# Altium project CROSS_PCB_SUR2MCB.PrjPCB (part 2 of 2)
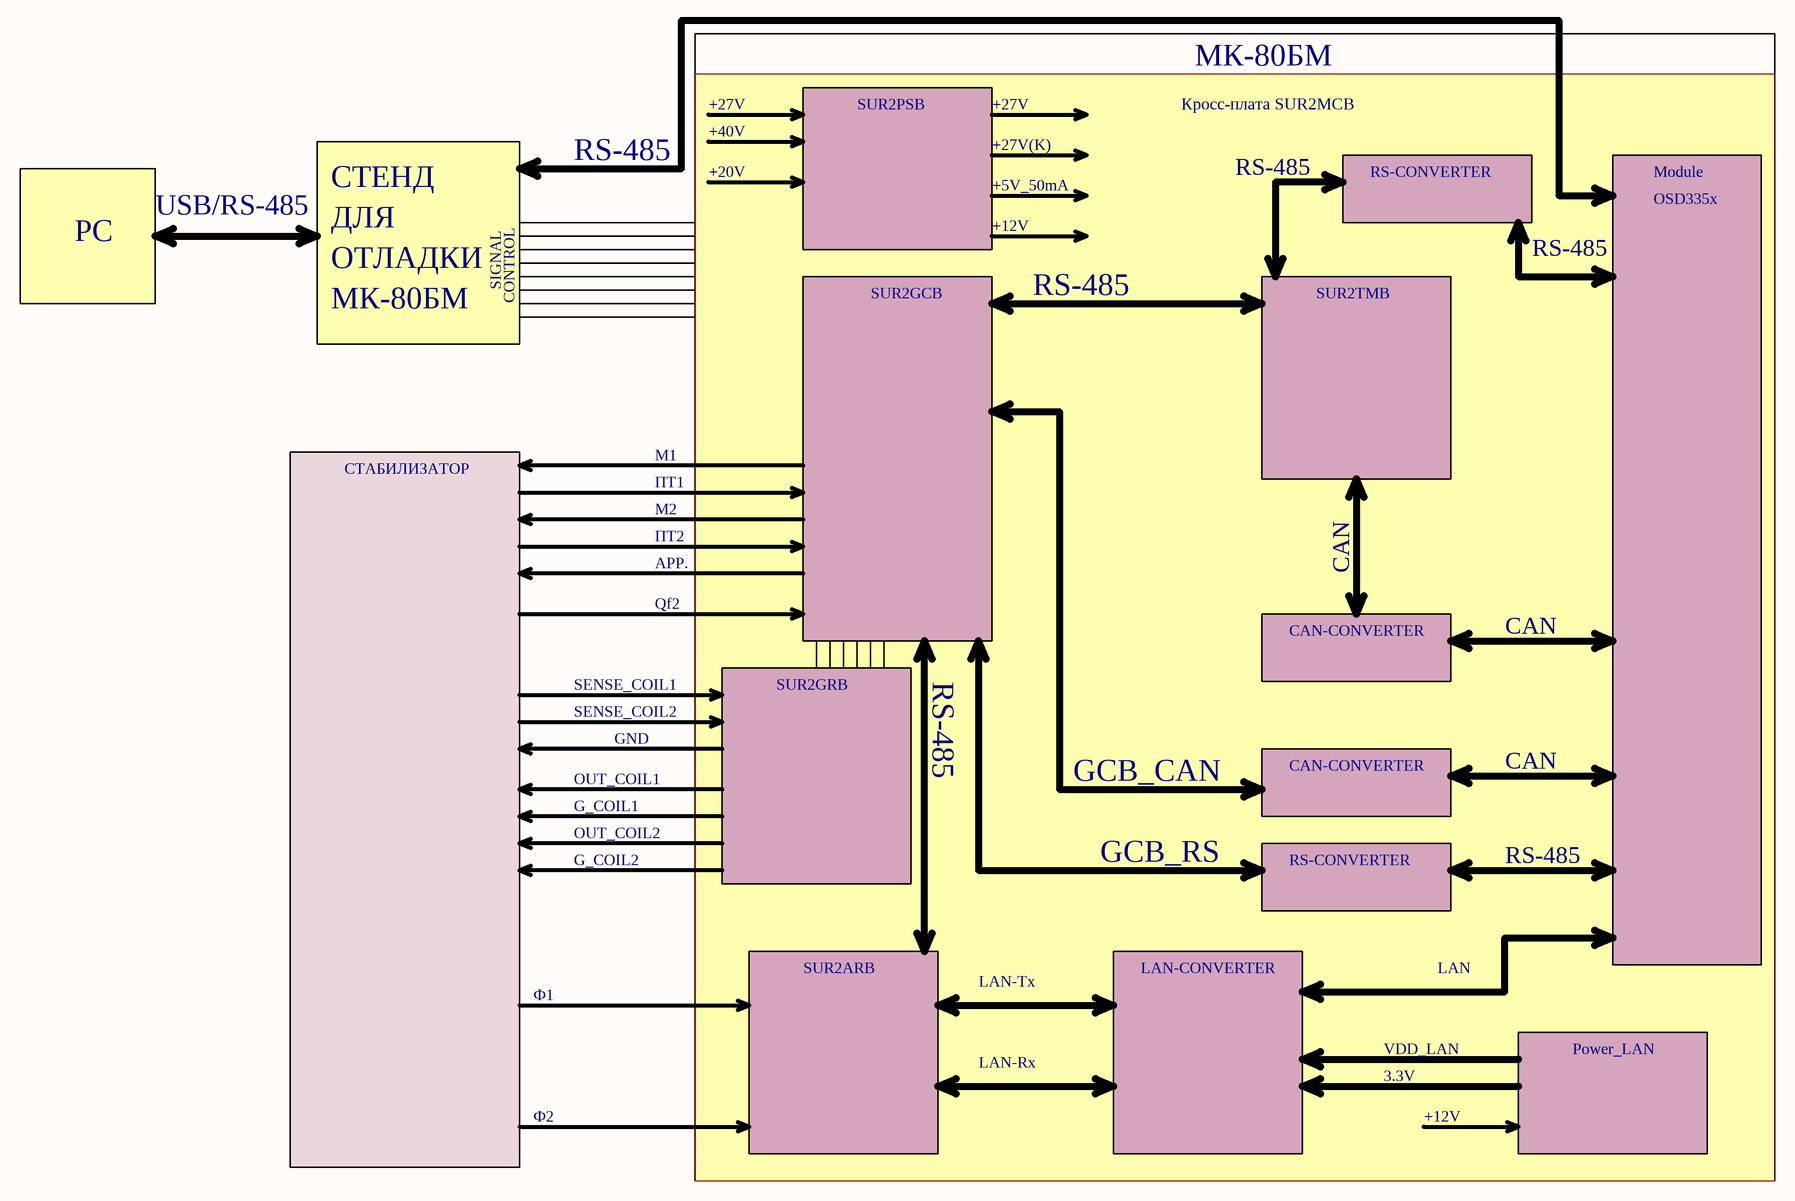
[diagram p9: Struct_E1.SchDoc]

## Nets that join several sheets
+3.3V: SUR2MCB_P1_CONNECTORSPCBs (X14.34 X14.35), SUR2MCB_P4_CONVERTINTERFACES (5 pins)
+5V: SUR2MCB_P1_CONNECTORSPCBs (8 pins), SUR2MCB_P5_PC (D10.3 D12.3 R66.1), SUR2MCB_P3_POWERETHERNNET (7 pins), SUR2MCB_P4_CONVERTINTERFACES (D4.3 D7.3 R54.1 R61.1)
+6V: SUR2MCB_P1_CONNECTORSPCBs (X14.5 X14.6), SUR2MCB_P3_POWERETHERNNET (5 pins), SUR2MCB_P4_CONVERTINTERFACES (D6.10)
+12V: MAINSHEET (X1.7 X11.22 X11.47), SUR2MCB_P1_CONNECTORSPCBs (5 pins), SUR2MCB_P3_POWERETHERNNET (5 pins)
-12V: MAINSHEET (X1.4 X11.19 X11.44), SUR2MCB_P1_CONNECTORSPCBs (5 pins)
GROUND_TO_COIL1: MAINSHEET (X3.7 X11.7 X11.32), SUR2MCB_P1_CONNECTORSPCBs (X16.21 X16.22)
GROUND_TO_COIL2: MAINSHEET (X3.5 X11.5 X11.30), SUR2MCB_P1_CONNECTORSPCBs (X16.25 X16.26)
OUTPUT_TO_COIL1: MAINSHEET (X3.6 X11.6 X11.31), SUR2MCB_P1_CONNECTORSPCBs (X16.19 X16.20)
OUTPUT_TO_COIL2: MAINSHEET (X3.1 X11.1 X11.26), SUR2MCB_P1_CONNECTORSPCBs (X16.23 X16.24)
RMII1_REFCLK: SUR2MCB_P2_CONVETHERNET (R9.1), SUR2MCB_P5_PC (R65.2)
SENSE_COIL1: MAINSHEET (X3.4 X11.4 X11.29), SUR2MCB_P1_CONNECTORSPCBs (X16.13 X16.14)
SENSE_COIL2: MAINSHEET (X3.3 X11.3 X11.28), SUR2MCB_P1_CONNECTORSPCBs (X16.17 X16.18)
SYS_VDD3_3P3V: SUR2MCB_P2_CONVETHERNET (C9.2), SUR2MCB_P5_PC (X17.7 X17.8)
VDD_3.3V: SUR2MCB_P2_CONVETHERNET (15 pins), SUR2MCB_P5_PC (D10.5 D11.10 D12.5 R67.2), SUR2MCB_P3_POWERETHERNNET (5 pins), SUR2MCB_P4_CONVERTINTERFACES (D4.5 D7.5 R59.2)
VDD_5V: SUR2MCB_P5_PC (X17.5 X17.6), SUR2MCB_P3_POWERETHERNNET (C28.2 C29.2 L3.2)
VDD_PHY: SUR2MCB_P2_CONVETHERNET (6 pins), SUR2MCB_P3_POWERETHERNNET (C15.2 C16.2 C17.2 L2.2)
О1: MAINSHEET (30 pins), SUR2MCB_P1_CONNECTORSPCBs (56 pins), SUR2MCB_P2_CONVETHERNET (20 pins), SUR2MCB_P5_PC (9 pins), SUR2MCB_P3_POWERETHERNNET (28 pins), SUR2MCB_P4_CONVERTINTERFACES (10 pins)
alpha*I: MAINSHEET (X10.14), SUR2MCB_P1_CONNECTORSPCBs (X13.6)
alpha*II: MAINSHEET (X10.15), SUR2MCB_P1_CONNECTORSPCBs (X13.7)
deltaЦУ: MAINSHEET (X8.20), SUR2MCB_P1_CONNECTORSPCBs (X13.20)
GCB_CAN_N: SUR2MCB_P1_CONNECTORSPCBs (X12.48), SUR2MCB_P4_CONVERTINTERFACES (D4.6 R51.1)
GCB_CAN_P: SUR2MCB_P1_CONNECTORSPCBs (X12.47), SUR2MCB_P4_CONVERTINTERFACES (D4.7 R51.2)
GCB_R_RX485: SUR2MCB_P5_PC (X18.6), SUR2MCB_P4_CONVERTINTERFACES (D5.2 D6.1)
GCB_RS485_AB_N: SUR2MCB_P1_CONNECTORSPCBs (X12.42), SUR2MCB_P4_CONVERTINTERFACES (D6.8 R55.1 R57.2)
GCB_RS485_AB_P: SUR2MCB_P1_CONNECTORSPCBs (X12.41), SUR2MCB_P4_CONVERTINTERFACES (D6.9 R54.2 R55.2)
GCB_RS485_YZ_N: SUR2MCB_P1_CONNECTORSPCBs (X12.45), SUR2MCB_P4_CONVERTINTERFACES (D6.7)
GCB_RS485_YZ_P: SUR2MCB_P1_CONNECTORSPCBs (X12.44), SUR2MCB_P4_CONVERTINTERFACES (D6.6)
GCB_TM_CAN_N: SUR2MCB_P5_PC (D12.6), SUR2MCB_P4_CONVERTINTERFACES (D4.4)
GCB_TM_CAN_P: SUR2MCB_P5_PC (D12.7), SUR2MCB_P4_CONVERTINTERFACES (D4.1)
GCB_TM_DE485: SUR2MCB_P5_PC (X18.68), SUR2MCB_P4_CONVERTINTERFACES (D6.3 R56.1)
GCB_TM_RE485: SUR2MCB_P5_PC (X18.64), SUR2MCB_P4_CONVERTINTERFACES (D5.1 D6.2 R53.1)
GCB_TM_SILENT: SUR2MCB_P1_CONNECTORSPCBs (X12.49), SUR2MCB_P4_CONVERTINTERFACES (D4.8 R52.1)
GCB_TM_TX485: SUR2MCB_P5_PC (X18.8), SUR2MCB_P4_CONVERTINTERFACES (D6.4)
LAN_RX_N: SUR2MCB_P1_CONNECTORSPCBs (X14.15), SUR2MCB_P2_CONVETHERNET (5 pins)
LAN_RX_P: SUR2MCB_P1_CONNECTORSPCBs (X14.16), SUR2MCB_P2_CONVETHERNET (5 pins)
LAN_TX_N: SUR2MCB_P1_CONNECTORSPCBs (X14.13), SUR2MCB_P2_CONVETHERNET (5 pins)
LAN_TX_N: SUR2MCB_P1_CONNECTORSPCBs (X14.14), SUR2MCB_P2_CONVETHERNET (5 pins)
M_PC_RS485_A: MAINSHEET (X8.1), SUR2MCB_P5_PC (D11.9 R66.2 R68.2)
M_PC_RS485_B: MAINSHEET (X8.2), SUR2MCB_P5_PC (D11.8 R68.1 R69.1)
M_PC_RS485_Y: MAINSHEET (X8.15), SUR2MCB_P5_PC (D11.6)
M_PC_RS485_Z: MAINSHEET (X8.16), SUR2MCB_P5_PC (D11.7)
MDIO_CLK: SUR2MCB_P2_CONVETHERNET (D1.17), SUR2MCB_P5_PC (X18.30)
MDIO_DATA: SUR2MCB_P2_CONVETHERNET (D1.16 R11.1), SUR2MCB_P5_PC (X18.10)
phiI: MAINSHEET (X8.13), SUR2MCB_P1_CONNECTORSPCBs (X13.12)
phiII: MAINSHEET (X8.14), SUR2MCB_P1_CONNECTORSPCBs (X13.13)
phiIIг: MAINSHEET (X10.21), SUR2MCB_P1_CONNECTORSPCBs (X13.11)
phiIг: MAINSHEET (X10.20), SUR2MCB_P1_CONNECTORSPCBs (X13.10)
RMII1_COL: SUR2MCB_P2_CONVETHERNET (R26.1), SUR2MCB_P5_PC (X18.20)
RMII1_CRS_DV: SUR2MCB_P2_CONVETHERNET (R28.1), SUR2MCB_P5_PC (X18.28)
RMII1_RXCLK: SUR2MCB_P2_CONVETHERNET (R20.1), SUR2MCB_P5_PC (X18.18)
RMII1_RXD0: SUR2MCB_P2_CONVETHERNET (R18.1), SUR2MCB_P5_PC (X18.12)
RMII1_RXD1: SUR2MCB_P2_CONVETHERNET (R17.1), SUR2MCB_P5_PC (X18.14)
RMII1_RXD2: SUR2MCB_P2_CONVETHERNET (R16.1), SUR2MCB_P5_PC (X18.16)
RMII1_RXD3: SUR2MCB_P2_CONVETHERNET (R14.1), SUR2MCB_P5_PC (X18.22)
RMII1_RXDV: SUR2MCB_P2_CONVETHERNET (R19.1), SUR2MCB_P5_PC (X18.34)
RMII1_RXERR: SUR2MCB_P2_CONVETHERNET (R21.1), SUR2MCB_P5_PC (X18.26)
RMII1_TXCLK: SUR2MCB_P2_CONVETHERNET (R22.1), SUR2MCB_P5_PC (X18.42)
RMII1_TXD0: SUR2MCB_P2_CONVETHERNET (D1.22), SUR2MCB_P5_PC (X18.38)
RMII1_TXD1: SUR2MCB_P2_CONVETHERNET (D1.23), SUR2MCB_P5_PC (X18.36)
RMII1_TXD2: SUR2MCB_P2_CONVETHERNET (D1.24), SUR2MCB_P5_PC (X18.40)
RMII1_TXD3: SUR2MCB_P2_CONVETHERNET (D1.25), SUR2MCB_P5_PC (X18.32)
RMII1_TXEN: SUR2MCB_P2_CONVETHERNET (D1.21), SUR2MCB_P5_PC (X18.24)
sigmaf2: MAINSHEET (X2.1 X11.11 X11.36), SUR2MCB_P1_CONNECTORSPCBs (X12.25)
sigmaI: MAINSHEET (X10.18), SUR2MCB_P1_CONNECTORSPCBs (X13.8)
sigmaII: MAINSHEET (X10.19), SUR2MCB_P1_CONNECTORSPCBs (X13.9)
sigmaпол: MAINSHEET (X8.3), SUR2MCB_P1_CONNECTORSPCBs (X13.21)
TEST_CAN_N: SUR2MCB_P1_CONNECTORSPCBs (X13.48), SUR2MCB_P4_CONVERTINTERFACES (D7.4)
TEST_CAN_P: SUR2MCB_P1_CONNECTORSPCBs (X13.47), SUR2MCB_P4_CONVERTINTERFACES (D7.1)
TMB_CAN_N: SUR2MCB_P5_PC (D10.6), SUR2MCB_P4_CONVERTINTERFACES (D7.6 R58.1)
TMB_CAN_P: SUR2MCB_P5_PC (D10.7), SUR2MCB_P4_CONVERTINTERFACES (D7.7 R58.2)
TMB_R_RX485: SUR2MCB_P5_PC (X18.52), SUR2MCB_P4_CONVERTINTERFACES (D8.2 D9.1)
TMB_RS485_AB_N: SUR2MCB_P1_CONNECTORSPCBs (X13.42), SUR2MCB_P4_CONVERTINTERFACES (D9.8 R62.1 R64.2)
TMB_RS485_AB_P: SUR2MCB_P1_CONNECTORSPCBs (X13.41), SUR2MCB_P4_CONVERTINTERFACES (D9.9 R61.2 R62.2)
TMB_RS485_YZ_N: SUR2MCB_P1_CONNECTORSPCBs (X13.45), SUR2MCB_P4_CONVERTINTERFACES (D9.7)
TMB_RS485_YZ_P: SUR2MCB_P1_CONNECTORSPCBs (X13.44), SUR2MCB_P4_CONVERTINTERFACES (D9.6)
TMB_TM_DE485: SUR2MCB_P5_PC (X18.60), SUR2MCB_P4_CONVERTINTERFACES (D9.3 R63.1)
TMB_TM_RE485: SUR2MCB_P5_PC (X18.62), SUR2MCB_P4_CONVERTINTERFACES (D8.1 D9.2 R60.1)
TMB_TM_SILENT: SUR2MCB_P1_CONNECTORSPCBs (X13.49), SUR2MCB_P4_CONVERTINTERFACES (D7.8 R59.1)
TMB_TM_TX485: SUR2MCB_P5_PC (X18.54), SUR2MCB_P4_CONVERTINTERFACES (D9.4)
¦sigmaпол¦: MAINSHEET (X10.12), SUR2MCB_P1_CONNECTORSPCBs (X13.22)
АЭ1: MAINSHEET (X8.25), SUR2MCB_P1_CONNECTORSPCBs (X13.18)
АЭ2: MAINSHEET (X8.26), SUR2MCB_P1_CONNECTORSPCBs (X13.19)
М1: MAINSHEET (X1.1 X11.16 X11.41), SUR2MCB_P1_CONNECTORSPCBs (X12.29)
М2: MAINSHEET (X1.2 X11.17 X11.42), SUR2MCB_P1_CONNECTORSPCBs (X12.30)
ОБМ.АРР.: MAINSHEET (X2.3 X11.13 X11.38), SUR2MCB_P1_CONNECTORSPCBs (X12.27)
ОК1: MAINSHEET (X2.2 X11.12 X11.37), SUR2MCB_P1_CONNECTORSPCBs (X12.26)
Оцу,sigmaпол: MAINSHEET (X8.22), SUR2MCB_P1_CONNECTORSPCBs (X13.23)
ПТ1: MAINSHEET (X1.5 X11.20 X11.45), SUR2MCB_P1_CONNECTORSPCBs (X12.33)
ПТ2: MAINSHEET (X1.6 X11.21 X11.46), SUR2MCB_P1_CONNECTORSPCBs (X12.32)
УР1: MAINSHEET (X8.9), SUR2MCB_P1_CONNECTORSPCBs (X13.14)
УР2: MAINSHEET (X8.19), SUR2MCB_P1_CONNECTORSPCBs (X13.15)
Ф1: MAINSHEET (X8.10), SUR2MCB_P1_CONNECTORSPCBs (X13.16)
Ф2: MAINSHEET (X8.23), SUR2MCB_P1_CONNECTORSPCBs (X13.17)
ФОН1: MAINSHEET (X8.11), SUR2MCB_P1_CONNECTORSPCBs (X13.24)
